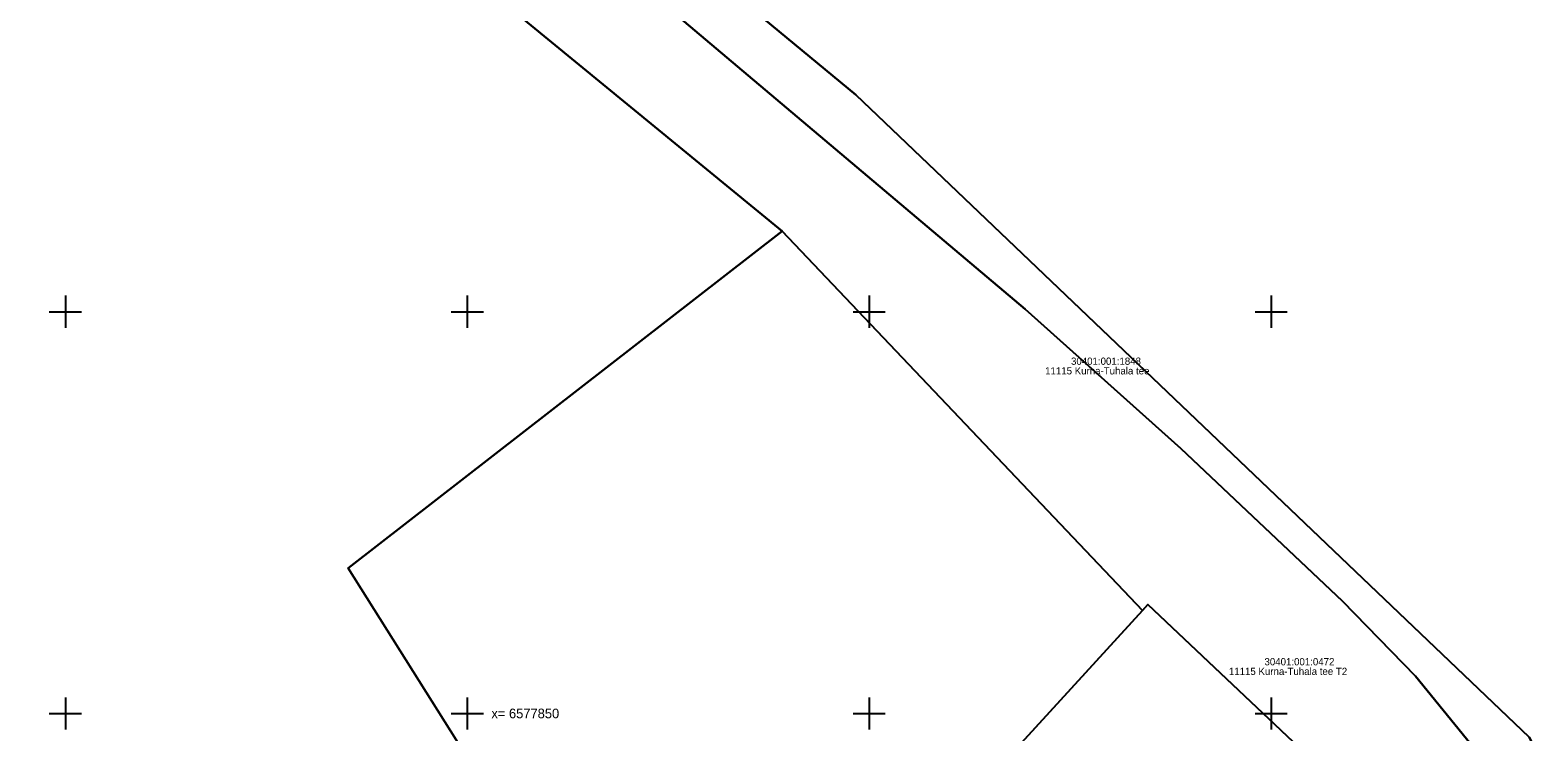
# Model space of a CAD drawing. Extents: x 543497 to 552146, y 6567125 to 6579845.
# Drawn here: x 546345.6 to 546533.2, y 6577847.7 to 6577935 of the extents above; entities that cross this region are included whole.
import ezdxf

# ---------------------------------------------------------------- set-up
doc = ezdxf.new("R2010")
doc.units = 0
doc.layers.add('xref_Kangru tee 1_geodeesia$0$PIIR', color=7, linetype='Continuous')
doc.layers.add('xref_Kangru tee 1_geodeesia$0$vork', color=7, linetype='Continuous')

# ---------------------------------------------------------------- blocks, each defined once
blk = doc.blocks.new('xref_Kangru tee 1_geodeesia$0$VKORIS')
for p, q in [((0, 4), (0, -4)), ((-4, 0), (4, 0))]:
    blk.add_line(p, q)

msp = doc.modelspace()

# ---------------------------------------------------------------- linework, layer by layer
at = {"layer": 'xref_Kangru tee 1_geodeesia$0$PIIR'}
for points in [[(546044, 6578353.3), (546163.95, 6578208.05), (546259.8, 6578095.33), (546272.31, 6578081.21), (546307.56, 6578041.43), (546352.17, 6578005.12), (546393.84, 6577964.11), (546469.41, 6577900.33), (546488.79, 6577882.98), (546508.9, 6577863.97), (546517.98, 6577854.65), (546527.76, 6577842.6), (546508.03, 6577841.48), (546484.68, 6577863.57), (546483.99, 6577862.81), (546439.17, 6577910.04), (546353.06, 6577980.64), (546342.34, 6577986.89), (546303.57, 6578024.94), (546269.27, 6578063.09), (546244.31, 6578092.34), (546063, 6578304.76)], [(546398.05, 6577968.6), (546410.54, 6577981.91), (546456.64, 6578031.02), (546521.16, 6578099.75), (546611.48, 6577846.34), (546540.2, 6577831.29), (546532.12, 6577847.04), (546448.34, 6577926.98), (546398.05, 6577968.6)], [(546343.49, 6577782.42), (546356.01, 6577800), (546324.91, 6577861.74), (546309.3, 6577910.03), (546301.14, 6577913.42), (546353.06, 6577980.64), (546439.17, 6577910.04), (546385.17, 6577868.1), (546425.19, 6577804.45), (546343.49, 6577782.42)], [(546393.84, 6577964.11), (546398.05, 6577968.6), (546448.34, 6577926.98), (546532.12, 6577847.04), (546551.12, 6577809.99), (546540.71, 6577817.81), (546535.64, 6577829.79), (546527.76, 6577842.6), (546517.98, 6577854.65), (546508.9, 6577863.97), (546488.79, 6577882.98), (546469.41, 6577900.33), (546393.84, 6577964.11)], [(546439.17, 6577910.04), (546483.99, 6577862.81), (546448.94, 6577824.49), (546452.89, 6577819.28), (546437.09, 6577804.4), (546426.72, 6577801.67), (546425.19, 6577804.45), (546385.17, 6577868.1), (546439.17, 6577910.04)], [(546455.94, 6577805.47), (546452.89, 6577819.28), (546448.94, 6577824.49), (546483.99, 6577862.81), (546484.68, 6577863.57), (546508.03, 6577841.48), (546479.51, 6577810.47), (546455.94, 6577805.47)]]:
    msp.add_lwpolyline(points, dxfattribs=at)

# ---------------------------------------------------------------- block references
at = {"layer": 'xref_Kangru tee 1_geodeesia$0$vork', "xscale": 0.5, "yscale": 0.5}
for p in [(546350, 6577900), (546400, 6577900), (546450, 6577900), (546500, 6577900), (546350, 6577850), (546400, 6577850), (546450, 6577850), (546500, 6577850)]:
    msp.add_blockref('xref_Kangru tee 1_geodeesia$0$VKORIS', p, dxfattribs=at)

# ---------------------------------------------------------------- texts
at = {"layer": 'xref_Kangru tee 1_geodeesia$0$PIIR'}
for s, p in [('11115 Kurna-Tuhala tee', (546471.89, 6577892.19)), ('30401:001:1848', (546475.11, 6577893.39)), ('11115 Kurna-Tuhala tee T2', (546494.75, 6577854.79)), ('30401:001:0472', (546499.18, 6577855.99))]:
    msp.add_text(s, height=0.9, dxfattribs=at).set_placement(p)
at = {"layer": 'xref_Kangru tee 1_geodeesia$0$vork'}
msp.add_text('x= 6577850', height=1.2, dxfattribs=at).set_placement((546403, 6577849.4))

doc.saveas('drawing.dxf')
